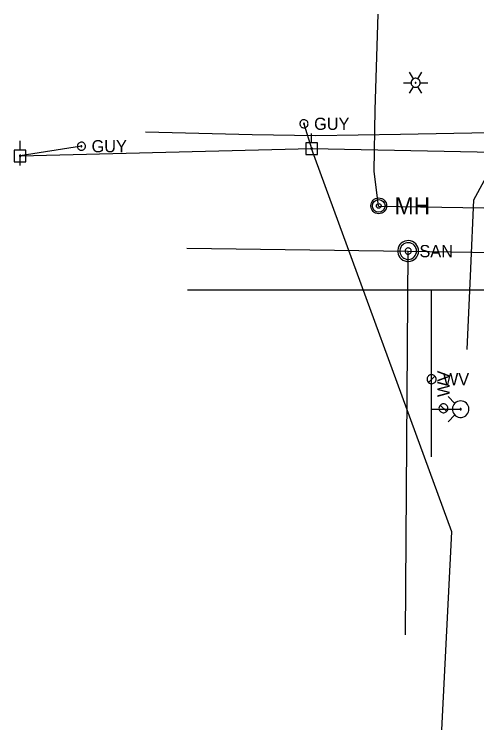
# Model space of a CAD drawing. Extents: x 596028 to 606371, y 330010 to 403088.
# Drawn here: x 604301.9 to 604448, y 332569.1 to 332794.8 of the extents above; entities that cross this region are included whole.
import ezdxf

# ---------------------------------------------------------------- set-up
doc = ezdxf.new("R2010")
doc.units = 0
for name, color, linetype in [('Default', 7, 'Continuous'), ('E_LTG', 7, 'Continuous'), ('E_UTL_E', 7, 'Continuous'), ('E_UTL_E_UG', 7, 'Continuous'), ('E_UTL_EGuyWire', 7, 'Continuous'), ('E_UTL_EPowerPole', 7, 'Continuous'), ('E_UTL_Overhead', 7, 'Continuous'), ('E_UTL_SAN_MH', 7, 'Continuous'), ('E_UTL_SAN_UG', 7, 'Continuous'), ('E_UTL_T_UG', 7, 'Continuous'), ('E_UTL_W', 7, 'Continuous'), ('E_UTL_W_UG', 7, 'Continuous'), ('E_UTL_WHydrant', 7, 'Continuous')]:
    doc.layers.add(name, color=color, linetype=linetype)

# ---------------------------------------------------------------- blocks, each defined once
blk = doc.blocks.new('MH')
at = {"layer": 'Default'}
for radius in [15.2, 12.2, 4.57]:
    blk.add_circle((0, 0), radius, dxfattribs=at)
blk.add_text('MH', height=32.92, dxfattribs=at).set_placement((30.5, -16.5))

msp = doc.modelspace()

# ---------------------------------------------------------------- linework, layer by layer
at = {"layer": 'E_LTG'}
for points in [[(604427.96, 332774.4), (604426.77, 332776.46)], [(604429.39, 332774.4), (604430.58, 332776.46)], [(604430.1, 332773.16), (604430.08, 332773.43), (604430, 332773.69), (604429.88, 332773.94), (604429.71, 332774.15), (604429.5, 332774.33), (604429.27, 332774.46), (604429.01, 332774.55), (604428.74, 332774.59), (604428.47, 332774.58), (604428.21, 332774.51), (604427.96, 332774.4), (604427.74, 332774.24), (604427.55, 332774.05), (604427.4, 332773.82), (604427.3, 332773.57), (604427.25, 332773.3), (604427.25, 332773.03), (604427.3, 332772.76), (604427.4, 332772.51), (604427.55, 332772.28), (604427.74, 332772.08), (604427.96, 332771.93), (604428.21, 332771.81), (604428.47, 332771.75), (604428.74, 332771.74), (604429.01, 332771.77), (604429.27, 332771.86), (604429.5, 332772), (604429.71, 332772.18), (604429.88, 332772.39), (604430, 332772.63), (604430.08, 332772.89), (604430.1, 332773.16)], [(604430.1, 332773.16), (604430.08, 332773.43), (604430, 332773.69), (604429.88, 332773.94), (604429.71, 332774.15), (604429.5, 332774.33), (604429.27, 332774.46), (604429.01, 332774.55), (604428.74, 332774.59), (604428.47, 332774.58), (604428.21, 332774.51), (604427.96, 332774.4), (604427.74, 332774.24), (604427.55, 332774.05), (604427.4, 332773.82), (604427.3, 332773.57), (604427.25, 332773.3), (604427.25, 332773.03), (604427.3, 332772.76), (604427.4, 332772.51), (604427.55, 332772.28), (604427.74, 332772.08), (604427.96, 332771.93), (604428.21, 332771.81), (604428.47, 332771.75), (604428.74, 332771.74), (604429.01, 332771.77), (604429.27, 332771.86), (604429.5, 332772), (604429.71, 332772.18), (604429.88, 332772.39), (604430, 332772.63), (604430.08, 332772.89), (604430.1, 332773.16)], [(604430.1, 332773.16), (604430.08, 332773.43), (604430, 332773.69), (604429.88, 332773.94), (604429.71, 332774.15), (604429.5, 332774.33), (604429.27, 332774.46), (604429.01, 332774.55), (604428.74, 332774.59), (604428.47, 332774.58), (604428.21, 332774.51), (604427.96, 332774.4), (604427.74, 332774.24), (604427.55, 332774.05), (604427.4, 332773.82), (604427.3, 332773.57), (604427.25, 332773.3), (604427.25, 332773.03), (604427.3, 332772.76), (604427.4, 332772.51), (604427.55, 332772.28), (604427.74, 332772.08), (604427.96, 332771.93), (604428.21, 332771.81), (604428.47, 332771.75), (604428.74, 332771.74), (604429.01, 332771.77), (604429.27, 332771.86), (604429.5, 332772), (604429.71, 332772.18), (604429.88, 332772.39), (604430, 332772.63), (604430.08, 332772.89), (604430.1, 332773.16)], [(604424.86, 332773.16), (604427.25, 332773.16)], [(604426.77, 332769.86), (604427.96, 332771.93)], [(604428.79, 332773.16), (604428.79, 332773.19), (604428.78, 332773.21), (604428.77, 332773.23), (604428.76, 332773.25), (604428.74, 332773.26), (604428.72, 332773.27), (604428.7, 332773.28), (604428.68, 332773.28), (604428.66, 332773.28), (604428.64, 332773.28), (604428.61, 332773.27), (604428.6, 332773.25), (604428.58, 332773.24), (604428.57, 332773.22), (604428.56, 332773.2), (604428.56, 332773.17), (604428.56, 332773.15), (604428.56, 332773.13), (604428.57, 332773.11), (604428.58, 332773.09), (604428.6, 332773.07), (604428.61, 332773.06), (604428.64, 332773.05), (604428.66, 332773.05), (604428.68, 332773.04), (604428.7, 332773.05), (604428.72, 332773.05), (604428.74, 332773.07), (604428.76, 332773.08), (604428.77, 332773.1), (604428.78, 332773.12), (604428.79, 332773.14), (604428.79, 332773.16)], [(604430.58, 332769.86), (604429.39, 332771.93)], [(604430.1, 332773.16), (604432.48, 332773.16)]]:
    msp.add_lwpolyline(points, dxfattribs=at)
at = {"layer": 'E_UTL_E_UG'}
for points in [[(604416.96, 332734.23), (604415.6, 332745.26), (604415.9, 332764.58), (604416.8, 332794.76)], [(604416.96, 332734.23), (604722.78, 332729.41), (604729.97, 332733.67)]]:
    msp.add_lwpolyline(points, dxfattribs=at)
at = {"layer": 'E_UTL_EGuyWire'}
for p, q in [((604393.4, 332760.22), (604395.83, 332752.41)), ((604323.13, 332753.16), (604303.82, 332750.1))]:
    msp.add_line(p, q, dxfattribs=at)
for points in [[(604394.69, 332760.22), (604394.66, 332760.47), (604394.6, 332760.7), (604394.48, 332760.92), (604394.33, 332761.11), (604394.15, 332761.27), (604393.94, 332761.39), (604393.71, 332761.47), (604393.47, 332761.51), (604393.22, 332761.49), (604392.98, 332761.44), (604392.76, 332761.33), (604392.56, 332761.19), (604392.4, 332761.02), (604392.26, 332760.81), (604392.17, 332760.59), (604392.13, 332760.35), (604392.13, 332760.1), (604392.17, 332759.86), (604392.26, 332759.64), (604392.4, 332759.43), (604392.56, 332759.25), (604392.76, 332759.11), (604392.98, 332759.01), (604393.22, 332758.95), (604393.47, 332758.94), (604393.71, 332758.98), (604393.94, 332759.06), (604394.15, 332759.18), (604394.33, 332759.34), (604394.48, 332759.53), (604394.6, 332759.75), (604394.66, 332759.98), (604394.69, 332760.22)], [(604393.56, 332760.22), (604393.56, 332760.25), (604393.55, 332760.28), (604393.54, 332760.31), (604393.52, 332760.33), (604393.5, 332760.35), (604393.47, 332760.37), (604393.44, 332760.38), (604393.41, 332760.38), (604393.38, 332760.38), (604393.35, 332760.38), (604393.32, 332760.36), (604393.3, 332760.34), (604393.28, 332760.32), (604393.26, 332760.3), (604393.25, 332760.27), (604393.24, 332760.24), (604393.24, 332760.21), (604393.25, 332760.18), (604393.26, 332760.15), (604393.28, 332760.12), (604393.3, 332760.1), (604393.32, 332760.08), (604393.35, 332760.07), (604393.38, 332760.06), (604393.41, 332760.06), (604393.44, 332760.07), (604393.47, 332760.08), (604393.5, 332760.09), (604393.52, 332760.11), (604393.54, 332760.14), (604393.55, 332760.16), (604393.56, 332760.19), (604393.56, 332760.22)], [(604324.41, 332753.16), (604324.39, 332753.4), (604324.32, 332753.63), (604324.21, 332753.85), (604324.06, 332754.04), (604323.87, 332754.2), (604323.66, 332754.32), (604323.43, 332754.4), (604323.19, 332754.44), (604322.95, 332754.43), (604322.71, 332754.37), (604322.49, 332754.27), (604322.29, 332754.13), (604322.12, 332753.95), (604321.99, 332753.75), (604321.9, 332753.52), (604321.85, 332753.28), (604321.85, 332753.04), (604321.9, 332752.8), (604321.99, 332752.57), (604322.12, 332752.36), (604322.29, 332752.19), (604322.49, 332752.05), (604322.71, 332751.94), (604322.95, 332751.89), (604323.19, 332751.88), (604323.43, 332751.91), (604323.66, 332751.99), (604323.87, 332752.11), (604324.06, 332752.27), (604324.21, 332752.46), (604324.32, 332752.68), (604324.39, 332752.91), (604324.41, 332753.16)], [(604323.29, 332753.16), (604323.29, 332753.19), (604323.28, 332753.22), (604323.27, 332753.24), (604323.25, 332753.27), (604323.22, 332753.29), (604323.2, 332753.3), (604323.17, 332753.31), (604323.14, 332753.32), (604323.11, 332753.32), (604323.08, 332753.31), (604323.05, 332753.3), (604323.03, 332753.28), (604323, 332753.26), (604322.99, 332753.23), (604322.98, 332753.2), (604322.97, 332753.17), (604322.97, 332753.14), (604322.98, 332753.11), (604322.99, 332753.08), (604323, 332753.06), (604323.03, 332753.04), (604323.05, 332753.02), (604323.08, 332753.01), (604323.11, 332753), (604323.14, 332753), (604323.17, 332753), (604323.2, 332753.01), (604323.22, 332753.03), (604323.25, 332753.05), (604323.27, 332753.07), (604323.28, 332753.1), (604323.29, 332753.13), (604323.29, 332753.16)]]:
    msp.add_lwpolyline(points, dxfattribs=at)
at = {"layer": 'E_UTL_EPowerPole'}
for points in [[(604395.8, 332754.25), (604395.8, 332757.16)], [(604303.79, 332751.94), (604303.79, 332754.85)], [(604397.64, 332754.25), (604393.96, 332754.25)], [(604393.96, 332754.25), (604393.96, 332750.56)], [(604397.64, 332750.56), (604397.64, 332754.25)], [(604305.63, 332751.94), (604301.94, 332751.94)], [(604301.94, 332751.94), (604301.94, 332748.25)], [(604305.63, 332748.25), (604305.63, 332751.94)], [(604396.07, 332752.41), (604396.07, 332752.45), (604396.05, 332752.49), (604396.03, 332752.54), (604396.01, 332752.57), (604395.97, 332752.6), (604395.93, 332752.62), (604395.89, 332752.64), (604395.84, 332752.64), (604395.8, 332752.64), (604395.76, 332752.63), (604395.71, 332752.61), (604395.68, 332752.59), (604395.65, 332752.55), (604395.62, 332752.52), (604395.6, 332752.47), (604395.6, 332752.43), (604395.6, 332752.38), (604395.6, 332752.34), (604395.62, 332752.3), (604395.65, 332752.26), (604395.68, 332752.23), (604395.71, 332752.2), (604395.76, 332752.18), (604395.8, 332752.17), (604395.84, 332752.17), (604395.89, 332752.17), (604395.93, 332752.19), (604395.97, 332752.21), (604396.01, 332752.24), (604396.03, 332752.28), (604396.05, 332752.32), (604396.07, 332752.36), (604396.07, 332752.41)], [(604304.06, 332750.1), (604304.05, 332750.14), (604304.04, 332750.19), (604304.02, 332750.23), (604303.99, 332750.26), (604303.96, 332750.29), (604303.92, 332750.31), (604303.88, 332750.33), (604303.83, 332750.34), (604303.79, 332750.33), (604303.74, 332750.32), (604303.7, 332750.3), (604303.66, 332750.28), (604303.63, 332750.24), (604303.61, 332750.21), (604303.59, 332750.16), (604303.58, 332750.12), (604303.58, 332750.07), (604303.59, 332750.03), (604303.61, 332749.99), (604303.63, 332749.95), (604303.66, 332749.92), (604303.7, 332749.89), (604303.74, 332749.87), (604303.79, 332749.86), (604303.83, 332749.86), (604303.88, 332749.87), (604303.92, 332749.88), (604303.96, 332749.9), (604303.99, 332749.93), (604304.02, 332749.97), (604304.04, 332750.01), (604304.05, 332750.05), (604304.06, 332750.1)], [(604393.96, 332750.56), (604397.64, 332750.56)], [(604301.94, 332748.25), (604305.63, 332748.25)]]:
    msp.add_lwpolyline(points, dxfattribs=at)
at = {"layer": 'E_UTL_Overhead'}
for p, q in [((604440.09, 332631.5), (604395.83, 332752.41)), ((604436.98, 332569.11), (604440.09, 332631.5))]:
    msp.add_line(p, q, dxfattribs=at)
msp.add_lwpolyline([(604303.82, 332747.1), (604303.82, 332750.1), (604395.83, 332752.41), (604557.99, 332749.19), (604648.21, 332744.48), (604719.99, 332742.51), (604741.26, 332741.22)], dxfattribs=at)
at = {"layer": 'E_UTL_SAN_MH'}
for points in [[(604429.61, 332720.08), (604429.55, 332720.71), (604429.37, 332721.31), (604429.09, 332721.87), (604428.7, 332722.36), (604428.22, 332722.77), (604427.68, 332723.08), (604427.09, 332723.29), (604426.47, 332723.38), (604425.84, 332723.35), (604425.23, 332723.2), (604424.66, 332722.94), (604424.15, 332722.58), (604423.72, 332722.12), (604423.38, 332721.59), (604423.14, 332721.01), (604423.02, 332720.4), (604423.02, 332719.77), (604423.14, 332719.15), (604423.38, 332718.57), (604423.72, 332718.04), (604424.15, 332717.59), (604424.66, 332717.22), (604425.23, 332716.96), (604425.84, 332716.82), (604426.47, 332716.79), (604427.09, 332716.88), (604427.68, 332717.08), (604428.22, 332717.39), (604428.7, 332717.81), (604429.09, 332718.3), (604429.37, 332718.86), (604429.55, 332719.46), (604429.61, 332720.08)], [(604428.95, 332720.08), (604428.9, 332720.58), (604428.76, 332721.06), (604428.53, 332721.51), (604428.22, 332721.9), (604427.84, 332722.23), (604427.41, 332722.48), (604426.93, 332722.65), (604426.44, 332722.72), (604425.93, 332722.7), (604425.45, 332722.58), (604424.99, 332722.37), (604424.58, 332722.08), (604424.23, 332721.71), (604423.96, 332721.29), (604423.78, 332720.83), (604423.68, 332720.33), (604423.68, 332719.83), (604423.78, 332719.34), (604423.96, 332718.87), (604424.23, 332718.45), (604424.58, 332718.09), (604424.99, 332717.8), (604425.45, 332717.59), (604425.93, 332717.47), (604426.44, 332717.45), (604426.93, 332717.52), (604427.41, 332717.68), (604427.84, 332717.93), (604428.22, 332718.26), (604428.53, 332718.66), (604428.76, 332719.1), (604428.9, 332719.58), (604428.95, 332720.08)], [(604427.3, 332720.08), (604427.28, 332720.27), (604427.23, 332720.45), (604427.14, 332720.62), (604427.03, 332720.77), (604426.88, 332720.89), (604426.72, 332720.98), (604426.54, 332721.04), (604426.36, 332721.07), (604426.17, 332721.06), (604425.99, 332721.02), (604425.81, 332720.94), (604425.66, 332720.83), (604425.53, 332720.69), (604425.43, 332720.54), (604425.36, 332720.36), (604425.32, 332720.18), (604425.32, 332719.99), (604425.36, 332719.8), (604425.43, 332719.63), (604425.53, 332719.47), (604425.66, 332719.33), (604425.81, 332719.23), (604425.99, 332719.15), (604426.17, 332719.1), (604426.36, 332719.09), (604426.54, 332719.12), (604426.72, 332719.18), (604426.88, 332719.28), (604427.03, 332719.4), (604427.14, 332719.55), (604427.23, 332719.71), (604427.28, 332719.9), (604427.3, 332720.08)]]:
    msp.add_lwpolyline(points, dxfattribs=at)
at = {"layer": 'E_UTL_SAN_UG'}
msp.add_line((604426.3, 332720.08), (604737.44, 332715.28), dxfattribs=at)
for points in [[(604356.46, 332720.96), (604426.3, 332720.08)], [(604425.44, 332599.04), (604426.3, 332720.08)]]:
    msp.add_lwpolyline(points, dxfattribs=at)
at = {"layer": 'E_UTL_T_UG'}
for points in [[(604343.4, 332757.65), (604377.02, 332756.84), (604397.2, 332756.55), (604423.85, 332756.95), (604452.03, 332757.46), (604491.14, 332756.02), (604514.73, 332754.97), (604562.12, 332754.56), (604576.81, 332753.78), (604626.24, 332752.96), (604667.79, 332752.28)], [(604444.92, 332689.06), (604446.05, 332714.53), (604447, 332736.21), (604454.21, 332749.36), (604460.95, 332753.83), (604468.4, 332756.86)]]:
    msp.add_lwpolyline(points, dxfattribs=at)
at = {"layer": 'E_UTL_W'}
for points in [[(604435.14, 332679.65), (604435.12, 332679.92), (604435.04, 332680.18), (604434.92, 332680.42), (604434.75, 332680.64), (604434.54, 332680.81), (604434.31, 332680.95), (604434.05, 332681.04), (604433.78, 332681.08), (604433.51, 332681.06), (604433.25, 332681), (604433, 332680.89), (604432.78, 332680.73), (604432.6, 332680.53), (604432.45, 332680.31), (604432.35, 332680.05), (604432.3, 332679.79), (604432.3, 332679.52), (604432.35, 332679.25), (604432.45, 332679), (604432.6, 332678.77), (604432.78, 332678.58), (604433, 332678.42), (604433.25, 332678.31), (604433.51, 332678.24), (604433.78, 332678.23), (604434.05, 332678.27), (604434.31, 332678.36), (604434.54, 332678.49), (604434.75, 332678.67), (604434.92, 332678.88), (604435.04, 332679.12), (604435.12, 332679.38), (604435.14, 332679.65)], [(604432.71, 332678.64), (604434.72, 332680.66)], [(604437.46, 332671.91), (604437.19, 332671.89), (604436.93, 332671.81), (604436.69, 332671.69), (604436.48, 332671.52), (604436.3, 332671.31), (604436.16, 332671.08), (604436.07, 332670.82), (604436.04, 332670.55), (604436.05, 332670.28), (604436.11, 332670.02), (604436.23, 332669.77), (604436.38, 332669.55), (604436.58, 332669.37), (604436.81, 332669.22), (604437.06, 332669.12), (604437.32, 332669.07), (604437.6, 332669.07), (604437.86, 332669.12), (604438.11, 332669.22), (604438.34, 332669.37), (604438.54, 332669.55), (604438.69, 332669.77), (604438.81, 332670.02), (604438.87, 332670.28), (604438.88, 332670.55), (604438.85, 332670.82), (604438.76, 332671.08), (604438.62, 332671.31), (604438.44, 332671.52), (604438.23, 332671.69), (604437.99, 332671.81), (604437.73, 332671.89), (604437.46, 332671.91)], [(604438.47, 332669.48), (604436.45, 332671.49)]]:
    msp.add_lwpolyline(points, dxfattribs=at)
at = {"layer": 'E_UTL_W_UG'}
for p, q in [((604356.64, 332707.84), (604433.72, 332707.84)), ((604433.72, 332670.21), (604442.9, 332670.21))]:
    msp.add_line(p, q, dxfattribs=at)
for points in [[(604433.72, 332655.14), (604433.72, 332707.84)], [(604433.72, 332707.84), (604452.27, 332707.84), (604557.89, 332691.73)]]:
    msp.add_lwpolyline(points, dxfattribs=at)
at = {"layer": 'E_UTL_WHydrant'}
for points in [[(604441.04, 332672.05), (604438.9, 332674.19)], [(604442.88, 332672.83), (604442.38, 332672.78), (604441.91, 332672.64), (604441.46, 332672.42), (604441.07, 332672.11), (604440.74, 332671.73), (604440.49, 332671.3), (604440.33, 332670.83), (604440.26, 332670.33), (604440.28, 332669.84), (604440.4, 332669.35), (604440.61, 332668.9), (604440.9, 332668.49), (604441.26, 332668.15), (604441.68, 332667.88), (604442.14, 332667.69), (604442.63, 332667.6), (604443.13, 332667.6), (604443.62, 332667.69), (604444.08, 332667.88), (604444.5, 332668.15), (604444.86, 332668.49), (604445.15, 332668.9), (604445.36, 332669.35), (604445.48, 332669.84), (604445.5, 332670.33), (604445.43, 332670.83), (604445.27, 332671.3), (604445.02, 332671.73), (604444.69, 332672.11), (604444.3, 332672.42), (604443.85, 332672.64), (604443.38, 332672.78), (604442.88, 332672.83)], [(604442.88, 332670.41), (604442.84, 332670.41), (604442.81, 332670.4), (604442.77, 332670.38), (604442.74, 332670.35), (604442.72, 332670.33), (604442.7, 332670.29), (604442.68, 332670.26), (604442.68, 332670.22), (604442.68, 332670.18), (604442.69, 332670.14), (604442.71, 332670.11), (604442.73, 332670.08), (604442.76, 332670.05), (604442.79, 332670.03), (604442.82, 332670.02), (604442.86, 332670.01), (604442.9, 332670.01), (604442.94, 332670.02), (604442.97, 332670.03), (604443, 332670.05), (604443.03, 332670.08), (604443.05, 332670.11), (604443.07, 332670.14), (604443.08, 332670.18), (604443.08, 332670.22), (604443.07, 332670.26), (604443.06, 332670.29), (604443.04, 332670.33), (604443.02, 332670.35), (604442.99, 332670.38), (604442.95, 332670.4), (604442.92, 332670.41), (604442.88, 332670.41)], [(604441.04, 332668.38), (604438.9, 332666.23)]]:
    msp.add_lwpolyline(points, dxfattribs=at)

# ---------------------------------------------------------------- block references
at = {"layer": 'E_UTL_E', "xscale": 0.16404166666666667, "yscale": 0.16404166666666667}
msp.add_blockref('MH', (604417.02, 332734.34), dxfattribs=at)

# ---------------------------------------------------------------- texts
at = {"layer": 'E_UTL_EGuyWire'}
for p in [(604396.61, 332758.3), (604326.34, 332751.23)]:
    msp.add_text('GUY', height=3.85, dxfattribs=at).set_placement(p)
at = {"layer": 'E_UTL_SAN_MH'}
msp.add_text('SAN', height=3.849, dxfattribs=at).set_placement((604429.87, 332718.14))
at = {"layer": 'E_UTL_W'}
msp.add_text('WV', height=3.85, rotation=90, dxfattribs=at).set_placement((604439.39, 332674.05))
msp.add_text('WV', height=3.85, dxfattribs=at).set_placement((604437.28, 332677.73))

doc.saveas('drawing.dxf')
